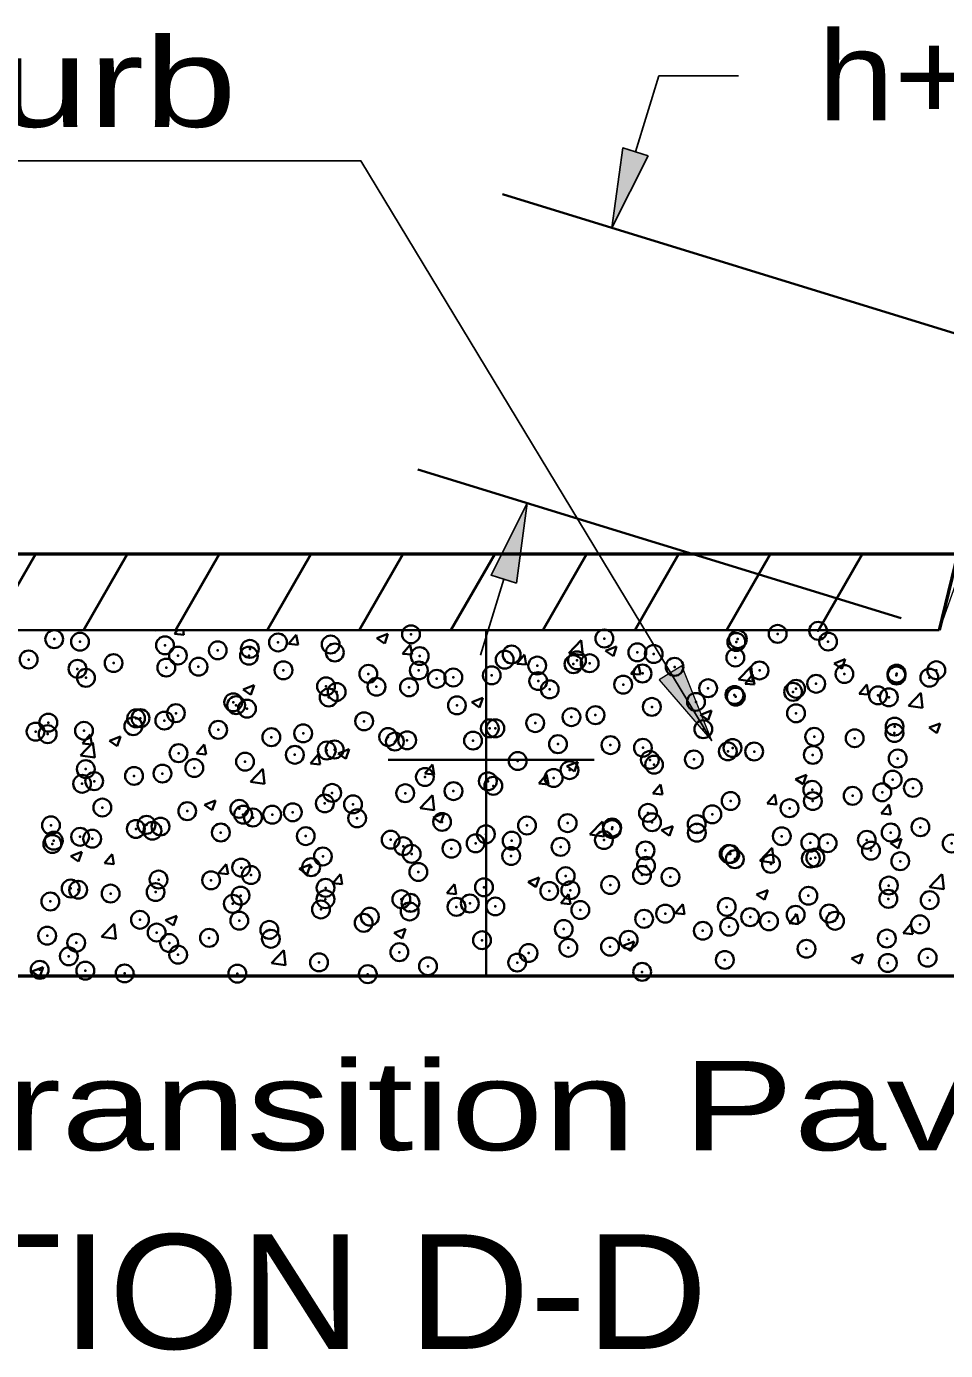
# Model space of a CAD drawing. Extents: x 14 to 49.3, y 28 to 50.
# Drawn here: x 27.563 to 29.007, y 46.498 to 48.577 of the extents above; entities that cross this region are included whole.
import ezdxf

# ---------------------------------------------------------------- set-up
doc = ezdxf.new("R2010")
doc.units = 0
doc.header["$LTSCALE"] = 0.056
doc.header["$PDMODE"] = 32
doc.header["$PDSIZE"] = 0.028
for name, color, linetype, lineweight in [('1', 7, 'Continuous', 35), ('3', 7, 'Continuous', 13), ('6', 7, 'Continuous', 13)]:
    doc.layers.add(name, color=color, linetype=linetype, lineweight=lineweight)

msp = doc.modelspace()

# ---------------------------------------------------------------- hatches: boundary and pattern name
at = {"layer": '1'}
for points in [[(28.5395, 48.37425), (28.49967, 48.38658), (28.48283, 48.26092), (28.48283, 48.26092)], [(28.33283, 47.703), (28.293, 47.71542), (28.34967, 47.82875), (28.34967, 47.82875)]]:
    msp.add_hatch(color=256, dxfattribs=at).paths.add_polyline_path(points)
at = {"layer": '3'}
msp.add_hatch(color=256, dxfattribs=at).paths.add_polyline_path([(28.5925, 47.57292), (28.55692, 47.55117), (28.64, 47.4555), (28.64, 47.4555)])

# ---------------------------------------------------------------- linework, layer by layer
at = {"layer": '1', "lineweight": 25}
for p, q in [((28.51958, 48.38042), (28.55642, 48.49992)), ((28.55642, 48.49992), (28.68142, 48.49992)), ((28.31292, 47.70925), (28.27617, 47.58975))]:
    msp.add_line(p, q, dxfattribs=at)
at = {"layer": '1'}
for p, q in [((29.07017, 48.08008), (28.31075, 48.31392)), ((28.93708, 47.64783), (28.17767, 47.88167)), ((28.99683, 47.62942), (26.06825, 47.62942)), ((27.76492, 47.62942), (27.76642, 47.62842)), ((27.76642, 47.62842), (27.76675, 47.62942)), ((27.79533, 47.62342), (27.80042, 47.62942)), ((27.79533, 47.62342), (27.81025, 47.62208)), ((27.81025, 47.62208), (27.80892, 47.62942)), ((28.11325, 47.61675), (28.13075, 47.6235)), ((28.12575, 47.60842), (28.13075, 47.6235)), ((28.28492, 47.62942), (28.28492, 47.08617)), ((27.97467, 47.60775), (27.98667, 47.62208)), ((27.97467, 47.60775), (27.98958, 47.60642)), ((27.98958, 47.60642), (27.98667, 47.62208)), ((28.11325, 47.61675), (28.12567, 47.60842)), ((28.15392, 47.592), (28.166, 47.60642)), ((28.16892, 47.59075), (28.166, 47.60642)), ((28.41508, 47.59333), (28.43458, 47.61358)), ((28.43733, 47.58983), (28.43458, 47.61358)), ((28.47258, 47.59675), (28.49008, 47.6035)), ((28.485, 47.58833), (28.49008, 47.6035)), ((28.15392, 47.592), (28.16892, 47.59075)), ((28.33325, 47.57633), (28.34533, 47.59075)), ((28.34825, 47.575), (28.34533, 47.59067)), ((28.41508, 47.59333), (28.43733, 47.58983)), ((28.47258, 47.59675), (28.485, 47.58842)), ((28.83183, 47.57675), (28.84933, 47.5835)), ((28.84425, 47.56833), (28.84933, 47.58342)), ((28.33325, 47.57633), (28.34817, 47.57508)), ((28.51258, 47.56067), (28.52467, 47.575)), ((28.51258, 47.56067), (28.5275, 47.55933)), ((28.5275, 47.55933), (28.52467, 47.575)), ((28.68192, 47.55192), (28.70142, 47.57225)), ((28.70417, 47.5485), (28.70142, 47.57225)), ((28.83183, 47.57675), (28.84425, 47.56833)), ((28.83183, 47.57675), (28.84425, 47.56833)), ((27.90325, 47.53617), (27.92075, 47.54283)), ((27.91567, 47.52775), (27.92075, 47.54283)), ((28.68192, 47.55192), (28.70417, 47.5485)), ((28.69192, 47.545), (28.70392, 47.55933)), ((28.69192, 47.545), (28.70683, 47.54367)), ((28.70683, 47.54367), (28.70392, 47.55933)), ((28.87117, 47.52925), (28.88325, 47.54367)), ((28.88617, 47.528), (28.88325, 47.54367)), ((27.90325, 47.53617), (27.91567, 47.52775)), ((28.2625, 47.51617), (28.28, 47.52283)), ((28.2625, 47.51617), (28.28, 47.52283)), ((28.27492, 47.50775), (28.28, 47.52283)), ((28.87117, 47.52925), (28.88617, 47.528)), ((28.94875, 47.51058), (28.96825, 47.53083)), ((28.971, 47.50708), (28.96825, 47.53083)), ((28.2625, 47.51617), (28.27492, 47.50775)), ((28.62175, 47.49608), (28.63925, 47.50283)), ((28.63425, 47.48775), (28.63933, 47.50283)), ((28.94875, 47.51058), (28.971, 47.50708)), ((28.62175, 47.49608), (28.63425, 47.48775)), ((28.98108, 47.47608), (28.99858, 47.48283)), ((28.9935, 47.46767), (28.99858, 47.48283)), ((27.65067, 47.45108), (27.66275, 47.46542)), ((27.66567, 47.44975), (27.66275, 47.46542)), ((27.69317, 47.4555), (27.71067, 47.46225)), ((27.70558, 47.44708), (27.71067, 47.46225)), ((28.98108, 47.47608), (28.9935, 47.46767)), ((27.64783, 47.43258), (27.66733, 47.45283)), ((27.65067, 47.45108), (27.66567, 47.44975)), ((27.67008, 47.42908), (27.66733, 47.45283)), ((27.69317, 47.4555), (27.70558, 47.44717)), ((27.83, 47.43533), (27.84208, 47.44975)), ((27.845, 47.43408), (27.84208, 47.44975)), ((28.05242, 47.4355), (28.06992, 47.44225)), ((28.06492, 47.42708), (28.07, 47.44217)), ((27.64783, 47.43258), (27.67008, 47.42908)), ((27.83, 47.43533), (27.84492, 47.43408)), ((27.83, 47.43533), (27.84492, 47.43408)), ((28.00933, 47.41967), (28.02133, 47.434)), ((28.00933, 47.41967), (28.02425, 47.41833)), ((28.02425, 47.41833), (28.02142, 47.434)), ((28.05242, 47.4355), (28.06492, 47.42708)), ((28.45475, 47.42575), (28.13117, 47.42575)), ((28.18867, 47.404), (28.20067, 47.41833)), ((28.20358, 47.40267), (28.20067, 47.41833)), ((28.41175, 47.4155), (28.42925, 47.42217)), ((28.41175, 47.4155), (28.42417, 47.40708)), ((28.42417, 47.40708), (28.42925, 47.42217)), ((27.91467, 47.39117), (27.93408, 47.4115)), ((27.93692, 47.38775), (27.93417, 47.41142)), ((28.18867, 47.404), (28.20358, 47.40267)), ((28.36792, 47.38833), (28.38, 47.40267)), ((28.38292, 47.387), (28.38, 47.40267)), ((28.771, 47.39542), (28.7885, 47.40217)), ((28.771, 47.39542), (28.78342, 47.38708)), ((28.78342, 47.38708), (28.7885, 47.40217)), ((27.91467, 47.39117), (27.93692, 47.38775)), ((28.36792, 47.38833), (28.38292, 47.387)), ((28.54725, 47.37258), (28.55933, 47.387)), ((28.56225, 47.37133), (28.55933, 47.387)), ((27.84242, 47.35483), (27.85992, 47.36158)), ((27.84242, 47.35483), (27.85483, 47.3465)), ((27.85483, 47.3465), (27.85992, 47.36158)), ((28.18142, 47.34983), (28.20092, 47.37008)), ((28.20367, 47.34633), (28.20092, 47.37008)), ((28.54725, 47.37258), (28.56217, 47.37133)), ((28.72658, 47.35692), (28.73867, 47.37125)), ((28.72658, 47.35692), (28.7415, 47.35558)), ((28.7415, 47.35558), (28.73867, 47.37125)), ((28.90592, 47.34125), (28.91792, 47.35558)), ((28.92083, 47.33992), (28.918, 47.35558)), ((28.18142, 47.34983), (28.20367, 47.34633)), ((28.20167, 47.33483), (28.21917, 47.34158)), ((28.20167, 47.33483), (28.21408, 47.32642)), ((28.21408, 47.32642), (28.21917, 47.34158)), ((28.90592, 47.34125), (28.92083, 47.33992)), ((28.44825, 47.30842), (28.46775, 47.32867)), ((28.4705, 47.30492), (28.46775, 47.32867)), ((28.56092, 47.31483), (28.57842, 47.3215)), ((28.56092, 47.31483), (28.57342, 47.30642)), ((28.57342, 47.30642), (28.5785, 47.3215)), ((28.44825, 47.30842), (28.4705, 47.305)), ((28.92025, 47.29483), (28.93775, 47.3015)), ((28.92025, 47.29483), (28.93267, 47.28642)), ((28.93267, 47.28642), (28.93775, 47.3015)), ((27.63233, 47.27425), (27.64983, 47.28092)), ((27.63233, 47.27425), (27.64475, 47.26583)), ((27.64475, 47.26583), (27.64983, 47.28092)), ((27.68533, 47.263), (27.69742, 47.27733)), ((27.70033, 47.26167), (27.69742, 47.27733)), ((28.71508, 47.267), (28.73458, 47.28733)), ((28.73733, 47.26358), (28.73458, 47.28733)), ((27.68533, 47.263), (27.70033, 47.26167)), ((27.86467, 47.24733), (27.87675, 47.26167)), ((27.87967, 47.246), (27.87675, 47.26167)), ((27.99158, 47.25425), (28.00908, 47.26092)), ((27.99158, 47.25425), (28.00408, 47.24583)), ((28.00408, 47.24583), (28.00917, 47.26092)), ((28.71508, 47.267), (28.73733, 47.26358)), ((27.86467, 47.24733), (27.87967, 47.246)), ((28.044, 47.23167), (28.05608, 47.246)), ((28.044, 47.23167), (28.05892, 47.23033)), ((28.059, 47.23033), (28.05608, 47.246)), ((28.22333, 47.21592), (28.23533, 47.23033)), ((28.23825, 47.21467), (28.23542, 47.23033)), ((28.35092, 47.23417), (28.36842, 47.24092)), ((28.35092, 47.23417), (28.36333, 47.22583)), ((28.36333, 47.22575), (28.36842, 47.24092)), ((28.98192, 47.22567), (29.00133, 47.24592)), ((29.00417, 47.22217), (29.00142, 47.24592)), ((28.22333, 47.21592), (28.23825, 47.21467)), ((28.40267, 47.20025), (28.41467, 47.21458)), ((28.41758, 47.19892), (28.41467, 47.21458)), ((28.71017, 47.21417), (28.72767, 47.22092)), ((28.71017, 47.21417), (28.72258, 47.20575)), ((28.72267, 47.20575), (28.72767, 47.22092)), ((28.98192, 47.22567), (29.00408, 47.22217)), ((28.40267, 47.20025), (28.41758, 47.19892)), ((28.58192, 47.18458), (28.594, 47.19892)), ((28.59692, 47.18325), (28.594, 47.19892)), ((27.681, 47.14767), (27.70042, 47.16792)), ((27.70325, 47.14417), (27.7005, 47.16792)), ((27.78158, 47.17358), (27.79908, 47.18033)), ((27.78158, 47.17358), (27.794, 47.16517)), ((27.794, 47.16517), (27.79908, 47.18025)), ((28.58192, 47.18458), (28.59692, 47.18325)), ((28.76125, 47.16892), (28.77333, 47.18325)), ((28.76125, 47.16892), (28.77617, 47.16758)), ((28.77625, 47.16758), (28.77333, 47.18325)), ((28.77625, 47.16758), (28.77333, 47.18325)), ((28.94058, 47.15317), (28.95267, 47.16758)), ((28.9555, 47.15183), (28.95267, 47.16758)), ((27.681, 47.14767), (27.70325, 47.14417)), ((28.14083, 47.15358), (28.15833, 47.16025)), ((28.14083, 47.15358), (28.15325, 47.14517)), ((28.15325, 47.14517), (28.15833, 47.16025)), ((28.94058, 47.15317), (28.9555, 47.15192)), ((27.94783, 47.10625), (27.96725, 47.12658)), ((27.97, 47.10283), (27.96725, 47.12658)), ((28.50008, 47.1335), (28.51767, 47.14025)), ((28.50008, 47.1335), (28.51258, 47.12517)), ((28.51258, 47.12517), (28.51767, 47.14025)), ((27.94783, 47.10625), (27.97, 47.10283)), ((28.85942, 47.1135), (28.87692, 47.12025)), ((28.85942, 47.1135), (28.87183, 47.10508)), ((28.87183, 47.10508), (28.87692, 47.12025)), ((27.5715, 47.09292), (27.589, 47.09967)), ((27.5715, 47.09292), (27.5815, 47.08617)), ((27.5845, 47.08617), (27.589, 47.09967)), ((27.7295, 47.08617), (27.73208, 47.08933)), ((27.73267, 47.08617), (27.73217, 47.08933))]:
    msp.add_line(p, q, dxfattribs=at)
at = {"layer": '1', "lineweight": 40}
for p, q in [((27.50825, 47.62942), (27.57683, 47.74833)), ((27.65258, 47.62942), (27.72117, 47.74833)), ((27.79692, 47.62942), (27.8655, 47.74833)), ((27.94125, 47.62942), (28.00983, 47.74833)), ((28.08558, 47.62942), (28.15425, 47.74833)), ((28.22992, 47.62942), (28.29858, 47.74833)), ((28.37425, 47.62942), (28.44292, 47.74833)), ((28.51858, 47.62942), (28.58725, 47.74833)), ((28.66292, 47.62942), (28.73158, 47.74833)), ((28.80725, 47.62942), (28.87592, 47.74833))]:
    msp.add_line(p, q, dxfattribs=at)
at = {"layer": '1', "lineweight": 13}
msp.add_line((29.02792, 47.716), (28.99683, 47.62942), dxfattribs=at)
at = {"layer": '1', "lineweight": 25}
for points in [[(28.5395, 48.37425), (28.49967, 48.38658), (28.48283, 48.26092), (28.48283, 48.26092)], [(28.33283, 47.703), (28.293, 47.71542), (28.34967, 47.82875), (28.34967, 47.82875)]]:
    msp.add_lwpolyline(points, close=True, dxfattribs=at)
at = {"layer": '1', "lineweight": 53}
for points in [[(26.06008, 47.08617), (29.45792, 47.08617), (29.45792, 47.9605), (29.44175, 48.03692), (29.40133, 48.07933), (29.17475, 48.07933), (29.11008, 48.05392), (29.08583, 47.9945), (28.99683, 47.62942)], [(29.02583, 47.74833), (26.06825, 47.74833), (26.06825, 47.62942)]]:
    msp.add_lwpolyline(points, dxfattribs=at)
at = {"layer": '1'}
for p in [(27.6065, 47.61508), (27.647, 47.61108), (27.95817, 47.60992), (28.16708, 47.62275), (28.47092, 47.61608), (28.67833, 47.61058), (28.68058, 47.61508), (28.74317, 47.62333), (28.80675, 47.62817), (28.82242, 47.61125), (27.7805, 47.60542), (27.80083, 47.58925), (27.86342, 47.5975), (27.91242, 47.58908), (27.91392, 47.59975), (28.04083, 47.60675), (28.04742, 47.59417), (28.18083, 47.5885), (28.32517, 47.591), (28.52267, 47.59433), (28.5485, 47.59183), (27.56625, 47.58308), (27.643, 47.56842), (27.69975, 47.5775), (27.78258, 47.57042), (27.83317, 47.57183), (28.31433, 47.58283), (28.36542, 47.57358), (28.42225, 47.57583), (28.428, 47.58183), (28.44775, 47.57725), (28.58125, 47.57158), (28.67667, 47.58617), (27.65633, 47.55433), (27.96667, 47.56617), (28.10008, 47.56058), (28.17933, 47.566), (28.2075, 47.55283), (28.23358, 47.55492), (28.29392, 47.55825), (28.367, 47.54925), (28.53083, 47.56117), (28.71467, 47.56592), (28.84808, 47.56033), (28.92992, 47.558), (28.93, 47.561), (28.98158, 47.55467), (28.9925, 47.56625), (28.03358, 47.541), (28.05025, 47.53217), (28.11283, 47.54033), (28.164, 47.5395), (28.38508, 47.53617), (28.5005, 47.54367), (28.63392, 47.538), (28.67533, 47.52742), (28.76742, 47.53233), (28.77208, 47.53717), (28.80367, 47.545), (28.90083, 47.52675), (27.88775, 47.51592), (27.89233, 47.51133), (27.90942, 47.50592), (28.03775, 47.5235), (28.23925, 47.51108), (28.5455, 47.50867), (28.61483, 47.5165), (28.67742, 47.52475), (28.91792, 47.52375), (27.59725, 47.484), (27.73508, 47.49067), (27.742, 47.49092), (27.77958, 47.48717), (27.79767, 47.49883), (28.09342, 47.48608), (28.41917, 47.49267), (28.45692, 47.49575), (28.77208, 47.49867), (27.57717, 47.46983), (27.59617, 47.46592), (27.65325, 47.47117), (27.73075, 47.47833), (27.86417, 47.47267), (27.99767, 47.46708), (28.29083, 47.475), (28.29967, 47.475), (28.36225, 47.48325), (28.62633, 47.47367), (28.92675, 47.46767), (28.92692, 47.47775), (27.94767, 47.46108), (28.13108, 47.46142), (28.14175, 47.45425), (28.161, 47.45625), (28.26458, 47.45575), (28.398, 47.45017), (28.4805, 47.44867), (28.5315, 47.4445), (28.67225, 47.44417), (28.80067, 47.46175), (28.86417, 47.45942), (27.80183, 47.436), (27.90633, 47.42267), (27.9845, 47.4335), (28.03475, 47.44025), (28.04708, 47.44175), (28.33475, 47.42367), (28.54242, 47.42542), (28.61158, 47.42617), (28.66492, 47.43883), (28.70633, 47.43858), (28.79842, 47.43325), (28.93183, 47.42758), (27.65608, 47.411), (27.7765, 47.40392), (27.82658, 47.41275), (28.41617, 47.40942), (28.549, 47.41792), (27.65025, 47.38792), (27.66933, 47.392), (27.73192, 47.40025), (28.18892, 47.39858), (28.28783, 47.39183), (28.29642, 47.38467), (28.39117, 47.39708), (28.92392, 47.3945), (28.95567, 47.3815), (28.04317, 47.37358), (28.158, 47.37308), (28.23383, 47.37642), (28.66925, 47.36092), (28.79758, 47.3785), (28.79842, 47.36075), (28.861, 47.369), (28.90758, 47.37458), (27.68208, 47.35058), (27.8155, 47.34492), (27.89733, 47.34858), (27.90333, 47.33942), (27.949, 47.33933), (27.98133, 47.34317), (28.03167, 47.35708), (28.076, 47.35558), (28.53942, 47.34217), (28.6405, 47.34), (28.76183, 47.3495), (27.60133, 47.32267), (27.75158, 47.3235), (27.7735, 47.32067), (27.91875, 47.33492), (28.08242, 47.33367), (28.21592, 47.328), (28.34933, 47.32242), (28.41317, 47.32617), (28.48325, 47.31933), (28.54583, 47.3275), (28.616, 47.3245), (28.9675, 47.31967), (27.60575, 47.2985), (27.64717, 47.30467), (27.66617, 47.30167), (27.73475, 47.317), (27.76083, 47.31417), (27.86825, 47.31133), (28.00167, 47.30575), (28.13517, 47.30008), (28.28475, 47.30858), (28.32533, 47.2985), (28.47017, 47.2995), (28.48275, 47.31675), (28.61625, 47.31108), (28.74967, 47.3055), (28.88317, 47.29983), (28.92083, 47.31133), (27.60358, 47.29342), (28.15492, 47.28983), (28.16808, 47.27783), (28.23067, 47.28608), (28.26858, 47.29442), (28.40208, 47.28883), (28.5355, 47.28317), (28.66625, 47.27767), (28.66892, 47.2775), (28.79458, 47.29533), (28.82167, 47.29467), (28.88992, 47.28292), (29.01658, 47.29417), (27.90025, 47.25625), (28.01025, 47.257), (28.02867, 47.27383), (28.32442, 47.2745), (28.53633, 47.259), (28.67592, 47.26958), (28.73267, 47.26217), (28.79525, 47.27042), (28.80242, 47.27192), (28.93583, 47.26625), (27.77042, 47.2375), (27.85292, 47.23633), (27.9155, 47.24458), (28.17858, 47.24942), (28.41008, 47.24292), (28.53008, 47.24458), (28.57475, 47.24142), (27.63233, 47.2235), (27.64417, 47.2215), (27.69508, 47.2155), (27.76575, 47.21783), (28.03283, 47.22442), (28.28175, 47.22533), (28.38433, 47.21958), (28.4175, 47.22067), (28.48008, 47.22892), (28.91783, 47.22808), (27.60042, 47.20308), (27.887, 47.19942), (27.89925, 47.21225), (28.03267, 47.20658), (28.15192, 47.20658), (28.16617, 47.20092), (28.2385, 47.19458), (28.25958, 47.19992), (28.29958, 47.19533), (28.66317, 47.1945), (28.7915, 47.21208), (28.91717, 47.20717), (28.982, 47.20508), (27.74125, 47.17433), (27.89725, 47.173), (28.02558, 47.19058), (28.10233, 47.17917), (28.16492, 47.18742), (28.43308, 47.18967), (28.53333, 47.17575), (28.5665, 47.184), (28.7, 47.17842), (28.77142, 47.18217), (28.82417, 47.18425), (28.83342, 47.17275), (27.76742, 47.15425), (27.94442, 47.15842), (28.09275, 47.1695), (28.40708, 47.15975), (28.62558, 47.15708), (28.66692, 47.16358), (28.7295, 47.17183), (28.96683, 47.16708), (27.59542, 47.14933), (27.64108, 47.13825), (27.78717, 47.13775), (27.84975, 47.14592), (27.94692, 47.1445), (28.27867, 47.14217), (28.47975, 47.13208), (28.509, 47.14283), (28.91475, 47.14483), (27.62933, 47.11692), (27.80117, 47.1195), (28.14883, 47.12342), (28.35175, 47.12208), (28.41433, 47.13033), (28.66017, 47.11125), (28.7885, 47.12883), (28.97883, 47.11475), (27.58367, 47.09575), (27.65533, 47.09442), (27.71708, 47.09008), (27.89417, 47.08975), (28.02258, 47.10742), (28.19383, 47.10133), (28.334, 47.10708), (28.53025, 47.0925), (28.91625, 47.1065), (28.09917, 47.08883)]:
    msp.add_point(p, dxfattribs=at)
at = {"layer": '3', "lineweight": 25}
msp.add_lwpolyline([(28.64, 47.4555), (28.08833, 48.36625), (26.13083, 48.36625)], dxfattribs=at)
at = {"layer": '3'}
msp.add_lwpolyline([(28.5925, 47.57292), (28.55692, 47.55117), (28.64, 47.4555), (28.64, 47.4555)], close=True, dxfattribs=at)
at = {"layer": '6', "lineweight": 25}
for p, q in [((28.48283, 48.26092), (28.48292, 48.26092)), ((28.99683, 47.62942), (28.99692, 47.62942))]:
    msp.add_line(p, q, dxfattribs=at)

# ---------------------------------------------------------------- texts
at = {"layer": '1', "width": 1.15}
msp.add_text('h+2"', height=0.14, dxfattribs=at).set_placement((28.80642, 48.42992))
at = {"layer": '3'}
for s, height, width, p in [('Concrete Curb', 0.14, 1.4, (26.18892, 48.41958)), ('Concrete Transition Pavement', 0.14, 1.4, (26.23367, 46.81242)), ('SECTION D-D', 0.18, 1.1, (26.91225, 46.50033))]:
    msp.add_text(s, height=height, dxfattribs=dict(at, width=width)).set_placement(p)

doc.saveas('drawing.dxf')
